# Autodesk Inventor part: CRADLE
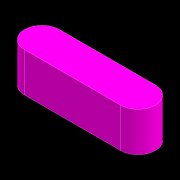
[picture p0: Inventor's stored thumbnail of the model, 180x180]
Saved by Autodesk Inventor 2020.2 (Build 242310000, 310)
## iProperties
Manager: PART
Company: 18
Created: 2020-10
Part Number: CRADLE
Material: Generic
Document SubType Name: Modeling
Designer: Apardo
Density: 1 g/cm^3
Appearance: Magenta
Description: CRADLE
Project: PLATE ROLLING MACHINE
Cost Center: 1
Engineer: STEEL C45
Stock Number: 1.14
Engr Approved By: D. JAEGER
Author: Apardo
Revision Number: 1.0
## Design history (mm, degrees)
sketch "Sketch1"
  geometry: L1 (7.5, 0)-(-7.5, 0); L2 (5.5, 2)-(-5.5, 2); L3 (-5.5, -2)-(5.5, -2); A1 r 2 centre (5.5, 0) between (5.5, -2) and (5.5, 2); A2 r 2 centre (-5.5, 0) between (-5.5, 2) and (-5.5, -2); 2 further points
  constraints: 8 end point, 6 point on circle, 4 tangent, 2 centre point, 2 point on line, 1 horizontal, 1 midpoint, 1 parallel
  dimensions: "d0" = 15 distance of L1.start L1.end; "d1" = 7.5 distance of point (0, 0) L1.start (= 0.5 x d0); "d2" = 4 distance between parallel lines of L3 L2
extrude "Extrusion1" new body sketch "Sketch1" stored distance "d3" = 4.5; taper "d4" = 0 deg
body "Solid1"
